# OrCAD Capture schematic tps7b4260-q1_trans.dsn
size Custom; title: TPS54233 :2A, 28V INPUT, STEP DOWN SWIFT; rev: 1.2; note: SBVS444 - January 2025
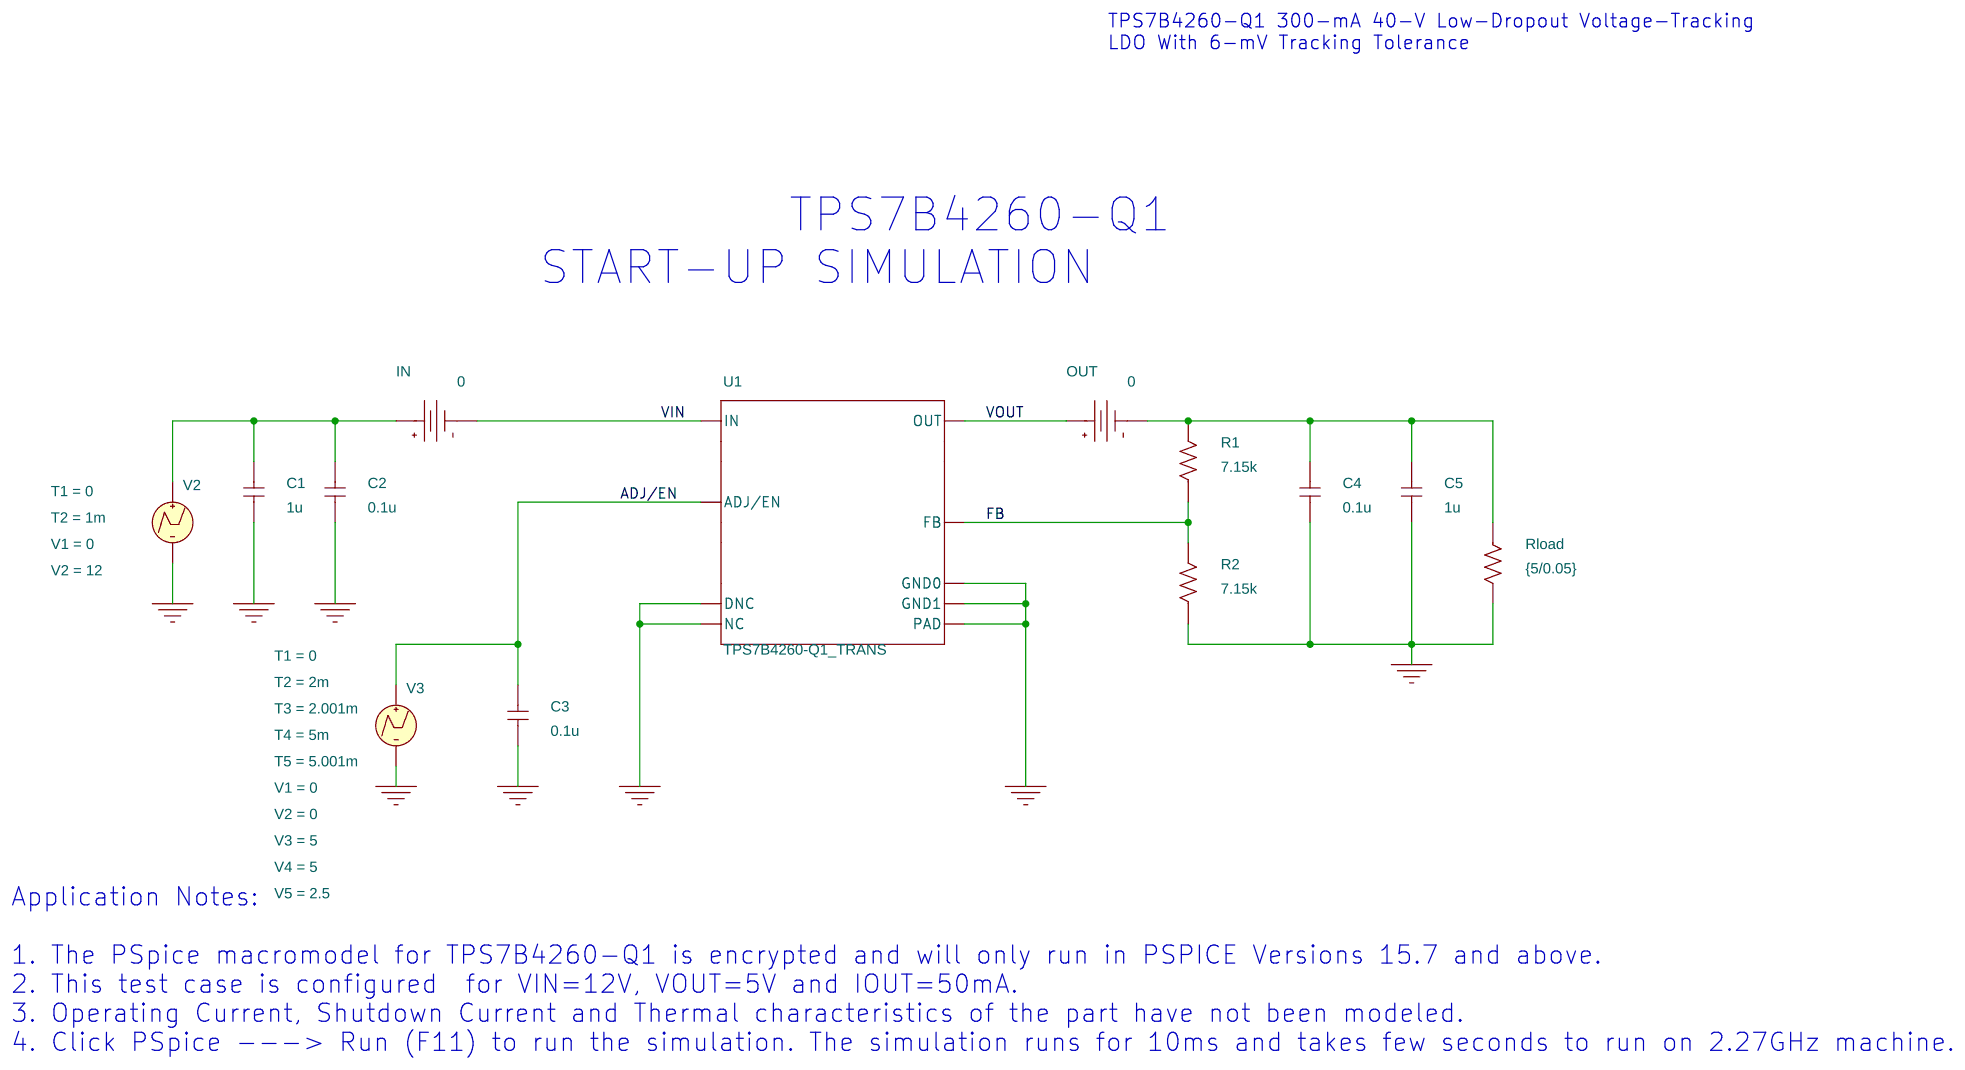
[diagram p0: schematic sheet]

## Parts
C1  1u  [RAD/CK05]
C2  0.1u  [RAD/CK05]
C3  0.1u  [RAD/CK05]
C4  0.1u  [RAD/CK05]
C5  1u  [RAD/CK05]
IN  VDC
OUT  VDC
R1  7.15k  [AX/RC05]
R2  7.15k  [AX/RC05]
Rload  {5/0.05}  [AX/RC05]
U1  TPS7B4260-Q1_TRANS
V2  VPWL
V3  VPWL

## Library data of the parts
C1-C5 = C
IN OUT = VDC: DC: 0
R1 R2 Rload = R
U1 = TPS7B4260-Q1_TRANS
V2 = VPWL: T1: 0; T2: 1m; V1: 0; V2: 12
V3 = VPWL: T1: 0; T2: 2m; T3: 2.001m; T4: 5m; T5: 5.001m; V1: 0; V2: 0; V3: 5; V4: 5; V5: 2.5

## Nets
VIN: IN.1(-) U1.IN
0: C1.2 C2.2 C3.2 C4.2 C5.2 R2.1 Rload.2 U1.DNC U1.GND0 U1.GND1 U1.NC U1.PAD V2.2(-) V3.2(-)
ADJ/EN: C3.1 U1.ADJ/EN V3.1(+)
FB: R1.1 R2.2 U1.FB
VOUT: OUT.0(+) U1.OUT
N309796: C4.1 C5.1 OUT.1(-) R1.2 Rload.1
N309868: C1.1 C2.1 IN.0(+) V2.1(+)

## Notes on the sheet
- TPS7B4260-Q1 300-mA 40-V Low-Dropout Voltage-Tracking
  LDO With 6-mV Tracking Tolerance
- TPS7B4260-Q1
  START-UP SIMULATION
- Application Notes:
  1. The PSpice macromodel for TPS7B4260-Q1 is encrypted and will only run in PSPICE Versions 15.7 and above.
  2. This test case is configured  for VIN=12V, VOUT=5V and IOUT=50mA.
  3. Operating Current, Shutdown Current and Thermal characteristics of the part have not been modeled.
  4. Click PSpice ---> Run (F11) to run the simulation. The simulation runs for 10ms and takes few seconds to run on 2.27GHz machine.
